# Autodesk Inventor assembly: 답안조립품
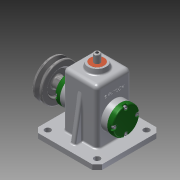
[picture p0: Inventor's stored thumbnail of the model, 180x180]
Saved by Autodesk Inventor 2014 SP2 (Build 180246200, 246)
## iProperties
Created: 2016-02
Part Number: 답안조립품
Document SubType Name: Assembly
Designer: apexhp001
Author: apexhp001
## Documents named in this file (16)
- C:\Users\apexhp001\Desktop\460212V1011\답안조립품.iam
- C:\Users\apexhp001\Desktop\460212V1011\본체.ipt
- C:\Users\apexhp001\Desktop\460212V1011\V벨트풀리.ipt
- C:\Users\apexhp001\Desktop\460212V1011\고정핀 1.2 x 10.ipt
- C:\Users\apexhp001\Desktop\460212V1011\뒤커버.ipt
- C:\Users\apexhp001\Desktop\460212V1011\링크.ipt
- C:\Users\apexhp001\Desktop\460212V1011\멈춤나사 M3x8.ipt
- C:\Users\apexhp001\Desktop\460212V1011\베어링 12 x 32 x 10.ipt
- C:\Users\apexhp001\Desktop\460212V1011\볼트 M4 x 12.ipt
- C:\Users\apexhp001\Desktop\460212V1011\부시.ipt
- C:\Users\apexhp001\Desktop\460212V1011\슬라이드.ipt
- C:\Users\apexhp001\Desktop\460212V1011\앞커버.ipt
- C:\Users\apexhp001\Desktop\460212V1011\오일실 12 25 7.ipt
- C:\Users\apexhp001\Desktop\460212V1011\키 4 x 4 x 10.ipt
- C:\Users\apexhp001\Desktop\460212V1011\편심축.ipt
- C:\Users\apexhp001\Desktop\460212V1011\핀 5 x 18.ipt
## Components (11 placed, 4 different names)
1. V벨트풀리:1 — 각도:4, 플러쉬:1
2. 고정핀 1.2 x 10:1
3. 핀 5 x 18:1
4. ISO 4762 M4 x 12:2 — 각도:3
5. ISO 4762 M4 x 12:3
6. ISO 4762 M4 x 12:4
7. ISO 4762 M4 x 12:5
8. ISO 4762 M4 x 12:1 — 각도:2
9. ISO 4762 M4 x 12:6
10. ISO 4762 M4 x 12:7
11. ISO 4762 M4 x 12:8
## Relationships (4: Angle 3, Flush 1)
- 각도:2 [Angle]: ISO 4762 M4 x 12:1
- 각도:3 [Angle]: ISO 4762 M4 x 12:2
- 각도:4 [Angle]: V벨트풀리:1
- 플러쉬:1 [Flush]: V벨트풀리:1
